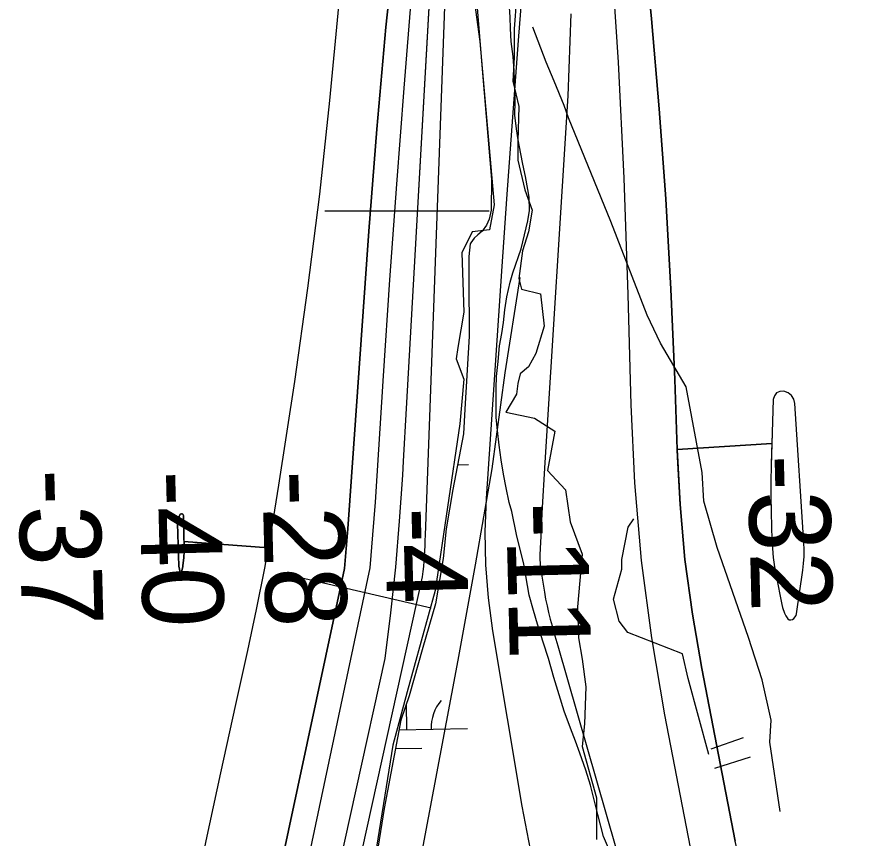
# Model space of a CAD drawing. Extents: x 3925854 to 3964121, y 224593 to 250589.
# Drawn here: x 3945031 to 3945726, y 239895 to 240571 of the extents above; entities that cross this region are included whole.
import ezdxf

# ---------------------------------------------------------------- set-up
doc = ezdxf.new("R2010")
doc.units = 0
for name, color, linetype in [('V-LEVE-TOET', 7, 'Continuous'), ('V-RIVR-EDGE', 7, 'Continuous'), ('V-RIVR-RANG', 7, 'Continuous'), ('V-RRAP-FSHR', 7, 'Continuous'), ('V-TOPO-DPTH', 7, 'Continuous'), ('V-TOPO-MINR', 7, 'Continuous'), ('V-WETL-SWMP', 7, 'Continuous')]:
    doc.layers.add(name, color=color, linetype=linetype)

msp = doc.modelspace()

# ---------------------------------------------------------------- linework, layer by layer
at = {"layer": 'V-LEVE-TOET'}
for p, q in [((3945420.097, 240410.848), (3945284.819, 240410.729)), ((3945372.172, 240083.938), (3945256.323, 240110.826)), ((3945600.835, 239963.524), (3945583.853, 240026.17)), ((3945602.861, 239968.214), (3945629.558, 239977.665)), ((3945605.89, 239952.374), (3945635.17, 239961.799))]:
    msp.add_line(p, q, dxfattribs=at)
for points in [[(3945659.785, 239916.825), (3945651.101, 239973.764), (3945652.355, 239991.837), (3945644.796, 240025.203), (3945633.603, 240059.825), (3945607.774, 240134.116), (3945596.921, 240172.227), (3945595.494, 240195.804), (3945582.241, 240266.317), (3945561.028, 240302.103), (3945550.02, 240325.17), (3945520.269, 240402.238), (3945485.435, 240487.72), (3945481.891, 240497.88), (3945473.71, 240517.846), (3945466.849, 240533.451), (3945456.111, 240562.23)], [(3945583.853, 240026.17), (3945579.2, 240046.435), (3945534.238, 240063.927), (3945527.191, 240073.424), (3945522.362, 240091.409), (3945529.307, 240116.112), (3945529.391, 240124.169), (3945534.38, 240150.869), (3945539.162, 240157.506)]]:
    msp.add_lwpolyline(points, dxfattribs=at)
at = {"layer": 'V-RIVR-EDGE'}
for points in [[(3945358.155, 241213.322), (3945377.046, 240948.836), (3945384.131, 240802.424), (3945395.151, 240665.458), (3945405.384, 240600.91), (3945412.469, 240550.532), (3945424.276, 240415.927), (3945420.34, 240395.461), (3945406.171, 240393.887), (3945397.513, 240376.569), (3945399.087, 240327.765), (3945394.364, 240298.64), (3945392.79, 240289.194), (3945399.087, 240272.664), (3945395.938, 240235.667), (3945375.472, 240098.701), (3945352.644, 240015.262), (3945340.837, 239971.181), (3945325.094, 239873.573), (3945284.948, 239657.891), (3945260.546, 239558.708), (3945201.509, 239254.864), (3945178.682, 239129.705), (3945119.644, 238862.07)], [(3945442.621, 240586.513), (3945440.655, 240560.957), (3945440.655, 240537.368), (3945439.672, 240517.71), (3945444.587, 240497.069), (3945443.604, 240468.565), (3945443.604, 240452.839), (3945449.501, 240428.266), (3945455.398, 240411.557), (3945452.45, 240393.865), (3945447.535, 240378.139), (3945444.587, 240355.532), (3945446.552, 240346.686), (3945462.279, 240342.755), (3945465.227, 240316.216), (3945458.347, 240293.61), (3945452.45, 240282.798), (3945445.569, 240276.9), (3945443.604, 240269.037), (3945442.621, 240260.191), (3945433.775, 240245.448), (3945457.364, 240240.533), (3945474.073, 240229.721), (3945468.176, 240197.286), (3945482.919, 240181.56), (3945486.851, 240155.021), (3945496.68, 240128.483), (3945492.748, 240085.236), (3945493.731, 240059.681), (3945496.68, 240041.988), (3945499.629, 240019.382), (3945498.646, 239988.912), (3945496.68, 239970.237), (3945508.475, 239927.972), (3945508.475, 239893.571)]]:
    msp.add_lwpolyline(points, dxfattribs=at)
at = {"layer": 'V-RRAP-FSHR'}
msp.add_lwpolyline([(3945160.841, 238864.481), (3945181.618, 238941.732), (3945201.145, 239019.304), (3945219.145, 239097.253), (3945234.464, 239175.769), (3945248.303, 239254.557), (3945261.424, 239333.473), (3945275.5, 239412.311), (3945288.779, 239491.118), (3945303.773, 239569.695), (3945319.141, 239648.206), (3945334.466, 239726.724), (3945349.781, 239805.244), (3945364.83, 239883.818), (3945379.788, 239962.406), (3945394.606, 240041.211), (3945408.796, 240119.751), (3945422.579, 240198.642), (3945433.143, 240277.804), (3945445.662, 240356.361)], dxfattribs=at)
at = {"layer": 'V-TOPO-DPTH'}
for points in [[(3945622.668, 239892.343), (3945595.043, 240034.436), (3945587.449, 240079.187), (3945581.292, 240124.1), (3945577.29, 240169.257), (3945574.724, 240214.575), (3945572.838, 240272.374), (3945569.701, 240346.668), (3945565.614, 240420.901), (3945560.105, 240495.042), (3945553.647, 240569.121), (3945522.628, 240889.417), (3945518.242, 240901.514), (3945511.507, 240910.884), (3945501.246, 240916.163), (3945488.634, 240918.716), (3945473.2, 240917.471), (3945457.854, 240915.636), (3945442.64, 240912.916), (3945427.514, 240909.605), (3945404.734, 240903.924), (3945392.342, 240898.155), (3945382.269, 240890.325)], [(3945652.853, 240219.537), (3945574.724, 240214.575), (3945572.838, 240272.374), (3945569.701, 240346.668), (3945565.614, 240420.901), (3945560.105, 240495.042), (3945553.647, 240569.121), (3945522.628, 240889.417), (3945518.242, 240901.514), (3945511.507, 240910.884), (3945501.246, 240916.163), (3945488.634, 240918.716), (3945473.2, 240917.471), (3945457.854, 240915.636), (3945442.64, 240912.916), (3945427.514, 240909.605), (3945404.734, 240903.924), (3945392.342, 240898.155), (3945382.269, 240890.325)], [(3945079.171, 239086.627), (3945133.342, 239136.688), (3945162.718, 239262.687), (3945163.374, 239265.574), (3945164.007, 239268.465), (3945164.608, 239271.364), (3945165.186, 239274.267), (3945165.74, 239277.176), (3945166.283, 239280.086), (3945166.811, 239282.999), (3945167.328, 239285.914), (3945334.284, 240042.622), (3945338.985, 240080.256), (3945343.092, 240117.946), (3945346.309, 240155.724), (3945348.932, 240193.558), (3945349.586, 240204.94), (3945352.082, 240248.51), (3945354.567, 240292.08), (3945357.035, 240335.652), (3945359.492, 240379.223), (3945387.62, 240879.833), (3945389.563, 240887.136), (3945392.897, 240893.289)], [(3945382.269, 240890.325), (3945375.675, 240879.403), (3945371.401, 240866.419), (3945353.948, 240729.516), (3945344.014, 240645.92), (3945335.034, 240562.229), (3945327.483, 240478.398), (3945320.885, 240394.472), (3945303.717, 240149.355), (3945302.417, 240133.051), (3945300.908, 240116.768), (3945125.024, 239293.971)], [(3945382.269, 240890.325), (3945375.675, 240879.403), (3945371.401, 240866.419), (3945353.948, 240729.516), (3945344.014, 240645.92), (3945335.034, 240562.229), (3945327.483, 240478.398), (3945320.885, 240394.472), (3945303.717, 240149.355), (3945302.417, 240133.051), (3945300.908, 240116.768), (3945125.024, 239293.971)], [(3945133.342, 239136.688), (3945162.718, 239262.687), (3945163.374, 239265.574), (3945164.007, 239268.465), (3945164.608, 239271.364), (3945165.186, 239274.267), (3945165.74, 239277.176), (3945166.283, 239280.086), (3945166.811, 239282.999), (3945167.328, 239285.914), (3945334.284, 240042.622), (3945338.985, 240080.256), (3945343.092, 240117.946), (3945346.309, 240155.724), (3945348.932, 240193.558), (3945349.586, 240204.94), (3945352.082, 240248.51), (3945354.567, 240292.08), (3945357.035, 240335.652), (3945359.492, 240379.223), (3945384.383, 240822.213), (3945384.759, 240828.906), (3945400.159, 240828.84), (3945399.952, 240820.735)], [(3945187.123, 239892.52), (3945199.08, 239948.652), (3945211.366, 240004.716), (3945221.319, 240049.193), (3945228.525, 240083.032), (3945235.263, 240116.959), (3945241.299, 240151.019), (3945246.867, 240185.166), (3945259.89, 240270.573), (3945270.821, 240347.584), (3945280.69, 240424.719), (3945288.965, 240502.042), (3945296.178, 240579.489)], [(3945238.242, 240133.769), (3945241.299, 240151.019), (3945246.867, 240185.166), (3945259.89, 240270.573), (3945270.821, 240347.584), (3945280.69, 240424.719), (3945288.965, 240502.042), (3945296.178, 240579.489)], [(3945487.39, 240573.115), (3945484.699, 240505.623), (3945465.89, 240203.929), (3945465.058, 240190.074), (3945464.27, 240176.216), (3945463.546, 240162.355), (3945462.865, 240148.491), (3945461.899, 240127.837), (3945461.847, 240124.306), (3945461.945, 240120.783), (3945462.269, 240117.274), (3945462.742, 240113.775), (3945465.536, 240097.14), (3945466.559, 240091.555), (3945467.692, 240085.993), (3945468.989, 240080.468), (3945470.396, 240074.967), (3945471.897, 240069.487), (3945473.414, 240064.011), (3945474.956, 240058.543), (3945476.515, 240053.079), (3945579.608, 239694.654)], [(3945487.39, 240573.115), (3945484.699, 240505.623), (3945465.89, 240203.929), (3945465.058, 240190.074), (3945464.27, 240176.216), (3945463.546, 240162.355), (3945462.865, 240148.491), (3945461.899, 240127.837), (3945461.847, 240124.306), (3945461.945, 240120.783), (3945462.269, 240117.274), (3945462.742, 240113.775), (3945465.536, 240097.14), (3945466.559, 240091.555), (3945467.692, 240085.993), (3945468.989, 240080.468), (3945470.396, 240074.967), (3945471.897, 240069.487), (3945473.414, 240064.011), (3945474.956, 240058.543), (3945476.515, 240053.079), (3945579.608, 239694.654)], [(3945652.65, 240212.908), (3945652.295, 240201.264), (3945652.04, 240188.653), (3945651.957, 240176.043), (3945652.133, 240163.433), (3945652.482, 240150.824), (3945652.865, 240140.751), (3945653.327, 240133.199), (3945654.02, 240125.674), (3945655.061, 240118.189), (3945656.332, 240110.731), (3945660.937, 240087.05), (3945661.528, 240084.621), (3945663.219, 240079.947), (3945664.319, 240077.702), (3945666.085, 240075.193), (3945667.143, 240074.552), (3945668.378, 240074.459), (3945669.729, 240074.733), (3945671.007, 240075.612), (3945672.736, 240077.975), (3945673.187, 240079.458), (3945678.32, 240115.312), (3945678.949, 240120.938), (3945679.344, 240126.573), (3945679.391, 240132.222), (3945679.205, 240137.88), (3945671.876, 240252.502), (3945670.835, 240256.169), (3945669.088, 240259.212), (3945666.282, 240261.319), (3945662.772, 240262.803), (3945659.426, 240262.455), (3945656.733, 240261.295)], [(3945656.733, 240261.295), (3945655.019, 240258.916), (3945653.957, 240255.724), (3945652.295, 240201.264), (3945652.04, 240188.653), (3945651.957, 240176.043), (3945652.133, 240163.433), (3945652.482, 240150.824), (3945652.865, 240140.751), (3945653.327, 240133.199), (3945654.02, 240125.674), (3945655.061, 240118.189), (3945656.332, 240110.731), (3945660.937, 240087.05), (3945661.528, 240084.621), (3945663.219, 240079.947), (3945664.319, 240077.702), (3945666.085, 240075.193), (3945667.143, 240074.552), (3945668.378, 240074.459), (3945669.729, 240074.733), (3945671.007, 240075.612), (3945672.736, 240077.975), (3945673.187, 240079.458), (3945678.32, 240115.312), (3945678.949, 240120.938), (3945679.344, 240126.573), (3945679.391, 240132.222), (3945679.205, 240137.88), (3945671.876, 240252.502), (3945670.835, 240256.169), (3945669.088, 240259.212), (3945666.282, 240261.319), (3945662.772, 240262.803), (3945659.426, 240262.455), (3945656.733, 240261.295)], [(3945656.733, 240261.295), (3945655.019, 240258.916), (3945653.957, 240255.724), (3945652.853, 240219.537)], [(3946535.235, 239352.689), (3945884.086, 239186.784), (3945883.307, 239189.346), (3945878.151, 239207.888), (3945873.664, 239226.604), (3945869.623, 239245.435), (3945862.419, 239282.22), (3945862.314, 239282.745), (3945862.206, 239283.27), (3945861.981, 239284.317), (3945861.604, 239286.425), (3945636.362, 239849.718), (3945630.635, 239863.506), (3945626.216, 239877.767), (3945622.668, 239892.343), (3945595.043, 240034.436), (3945587.449, 240079.187), (3945581.292, 240124.1), (3945577.29, 240169.257), (3945575.073, 240208.417), (3945574.724, 240214.575), (3945652.853, 240219.537), (3945652.65, 240212.908)], [(3945163.879, 240157.723), (3945163.473, 240155.773), (3945163.325, 240153.741), (3945164.399, 240118.509), (3945165.597, 240113.798), (3945165.906, 240113.463), (3945166.214, 240113.32), (3945166.521, 240113.465), (3945166.828, 240113.802), (3945167.797, 240118.241), (3945167.926, 240119.156), (3945168.406, 240123.362), (3945168.632, 240125.773), (3945168.859, 240130.606), (3945168.86, 240133.028), (3945168.323, 240160.458), (3945167.881, 240161.318), (3945167.32, 240161.807), (3945166.579, 240161.738), (3945165.719, 240161.298), (3945163.879, 240157.723)], [(3945238.076, 240132.835), (3945238.242, 240133.769), (3945168.744, 240138.944), (3945168.767, 240137.766), (3945168.86, 240133.028), (3945168.859, 240130.606), (3945168.632, 240125.773), (3945168.406, 240123.362), (3945167.926, 240119.156), (3945167.797, 240118.241), (3945166.828, 240113.802), (3945166.521, 240113.465), (3945166.214, 240113.32), (3945165.906, 240113.463), (3945165.597, 240113.798), (3945164.399, 240118.509), (3945163.325, 240153.741), (3945163.473, 240155.773), (3945163.879, 240157.723)], [(3945163.879, 240157.723), (3945165.719, 240161.298), (3945166.579, 240161.738), (3945167.32, 240161.807), (3945167.881, 240161.318), (3945168.323, 240160.458), (3945168.744, 240138.944), (3945238.242, 240133.769)], [(3944948.202, 238955.851), (3945050.084, 239272.016), (3945051.864, 239276.071), (3945054.107, 239279.778), (3945057.045, 239282.963), (3945060.447, 239285.8), (3945066.451, 239289.849), (3945068.634, 239291.611), (3945070.349, 239293.767), (3945070.943, 239295.494), (3945164.528, 239779.981), (3945175.661, 239836.285), (3945187.123, 239892.52), (3945199.08, 239948.652), (3945211.366, 240004.716), (3945221.319, 240049.193), (3945228.525, 240083.032), (3945235.263, 240116.959), (3945238.076, 240132.835)]]:
    msp.add_lwpolyline(points, dxfattribs=at)
at = {"layer": 'V-TOPO-MINR'}
for points in [[(3945382.269, 240890.325), (3945392.342, 240898.155), (3945404.734, 240903.924), (3945427.514, 240909.605), (3945442.64, 240912.916), (3945457.854, 240915.636), (3945473.2, 240917.471), (3945488.634, 240918.716), (3945501.246, 240916.163), (3945511.507, 240910.884), (3945518.242, 240901.514), (3945522.628, 240889.417), (3945553.647, 240569.121), (3945560.105, 240495.042), (3945565.614, 240420.901), (3945569.701, 240346.668), (3945572.838, 240272.374), (3945574.724, 240214.575), (3945577.29, 240169.257), (3945581.292, 240124.1), (3945587.449, 240079.187), (3945595.043, 240034.436), (3945622.668, 239892.343)], [(3945387.714, 240891.779), (3945395.379, 240897.921), (3945404.931, 240902.457), (3945422.708, 240906.891), (3945434.517, 240909.475), (3945446.394, 240911.599), (3945458.374, 240913.032), (3945470.422, 240914.004), (3945480.25, 240912.005), (3945488.234, 240907.879), (3945493.455, 240900.563), (3945496.833, 240891.12), (3945512.088, 240724.516), (3945519.869, 240629.092), (3945526.381, 240533.595), (3945530.992, 240437.986), (3945534.334, 240342.304), (3945536.601, 240251.512), (3945539.818, 240187.3), (3945545.167, 240123.32), (3945553.716, 240059.689), (3945564.398, 239996.29), (3945603.534, 239794.981)], [(3945133.342, 239136.688), (3945162.718, 239262.687), (3945163.374, 239265.574), (3945164.007, 239268.465), (3945164.608, 239271.364), (3945165.186, 239274.267), (3945165.74, 239277.176), (3945166.283, 239280.086), (3945166.811, 239282.999), (3945167.328, 239285.914), (3945334.284, 240042.622), (3945338.985, 240080.256), (3945343.092, 240117.946), (3945346.309, 240155.724), (3945348.932, 240193.558), (3945349.586, 240204.94), (3945352.082, 240248.51), (3945354.567, 240292.08), (3945357.035, 240335.652), (3945359.492, 240379.223), (3945387.62, 240879.833), (3945389.563, 240887.136), (3945392.897, 240893.289)], [(3945155.778, 239131.865), (3945184.493, 239264.7), (3945185.365, 239268.842), (3945186.189, 239272.994), (3945186.972, 239277.154), (3945187.719, 239281.32), (3945215.33, 239439.401), (3945218.985, 239457.037), (3945223.362, 239474.469), (3945228.823, 239491.591), (3945365.28, 240109.87), (3945365.809, 240114.117), (3945366.264, 240118.371), (3945366.608, 240122.635), (3945366.878, 240126.906), (3945367.084, 240131.183), (3945367.278, 240135.46), (3945367.455, 240139.738), (3945367.62, 240144.017), (3945394.863, 240886.629), (3945395.97, 240891.076), (3945397.939, 240894.824)], [(3945114.556, 239142.154), (3945144.386, 239261.072), (3945145.117, 239264.618), (3945145.647, 239268.185), (3945145.874, 239271.784), (3945145.893, 239275.571), (3945145.877, 239279.284), (3945146.016, 239282.985), (3945146.385, 239286.671), (3945146.909, 239290.346), (3945321.949, 240117.352), (3945324.353, 240144.333), (3945326.373, 240171.352), (3945333.024, 240275.244), (3945338.313, 240354.22), (3945343.91, 240433.174), (3945349.969, 240512.094), (3945356.336, 240590.991), (3945379.933, 240873.073), (3945382.88, 240883.229), (3945387.714, 240891.779)], [(3945125.024, 239293.971), (3945300.908, 240116.768), (3945302.417, 240133.051), (3945303.717, 240149.355), (3945320.885, 240394.472), (3945327.483, 240478.398), (3945335.034, 240562.229), (3945344.014, 240645.92), (3945353.948, 240729.516), (3945371.401, 240866.419), (3945375.675, 240879.403), (3945382.269, 240890.325)], [(3945448.88, 240614.527), (3945443.968, 240551.305), (3945439.196, 240488.073), (3945434.636, 240424.825), (3945430.217, 240361.567), (3945417.455, 240174.373), (3945416.557, 240147.009), (3945416.938, 240119.708), (3945419.239, 240092.502), (3945422.82, 240065.358), (3945447.031, 239921.213), (3945453.796, 239885.476)], [(3945187.123, 239892.52), (3945199.08, 239948.652), (3945211.366, 240004.716), (3945221.319, 240049.193), (3945228.525, 240083.032), (3945235.263, 240116.959), (3945241.299, 240151.019), (3945246.867, 240185.166), (3945259.89, 240270.573), (3945270.821, 240347.584), (3945280.69, 240424.719), (3945288.965, 240502.042), (3945296.178, 240579.489)], [(3945487.39, 240573.115), (3945484.699, 240505.623), (3945465.89, 240203.929), (3945465.058, 240190.074), (3945464.27, 240176.216), (3945463.546, 240162.355), (3945462.865, 240148.491), (3945461.899, 240127.837), (3945461.847, 240124.306), (3945461.945, 240120.783), (3945462.269, 240117.274), (3945462.742, 240113.775), (3945465.536, 240097.14), (3945466.559, 240091.555), (3945467.692, 240085.993), (3945468.989, 240080.468), (3945470.396, 240074.967), (3945471.897, 240069.487), (3945473.414, 240064.011), (3945474.956, 240058.543), (3945476.515, 240053.079), (3945579.608, 239694.654)], [(3945656.733, 240261.295), (3945655.019, 240258.916), (3945653.957, 240255.724), (3945652.295, 240201.264), (3945652.04, 240188.653), (3945651.957, 240176.043), (3945652.133, 240163.433), (3945652.482, 240150.824), (3945652.865, 240140.751), (3945653.327, 240133.199), (3945654.02, 240125.674), (3945655.061, 240118.189), (3945656.332, 240110.731), (3945660.937, 240087.05), (3945661.528, 240084.621), (3945663.219, 240079.947), (3945664.319, 240077.702), (3945666.085, 240075.193), (3945667.143, 240074.552), (3945668.378, 240074.459), (3945669.729, 240074.733), (3945671.007, 240075.612), (3945672.736, 240077.975), (3945673.187, 240079.458), (3945678.32, 240115.312), (3945678.949, 240120.938), (3945679.344, 240126.573), (3945679.391, 240132.222), (3945679.205, 240137.88), (3945671.876, 240252.502), (3945670.835, 240256.169), (3945669.088, 240259.212), (3945666.282, 240261.319), (3945662.772, 240262.803), (3945659.426, 240262.455), (3945656.733, 240261.295)], [(3945163.879, 240157.723), (3945163.473, 240155.773), (3945163.325, 240153.741), (3945164.399, 240118.509), (3945165.597, 240113.798), (3945165.906, 240113.463), (3945166.214, 240113.32), (3945166.521, 240113.465), (3945166.828, 240113.802), (3945167.797, 240118.241), (3945167.926, 240119.156), (3945168.406, 240123.362), (3945168.632, 240125.773), (3945168.859, 240130.606), (3945168.86, 240133.028), (3945168.323, 240160.458), (3945167.881, 240161.318), (3945167.32, 240161.807), (3945166.579, 240161.738), (3945165.719, 240161.298), (3945163.879, 240157.723)]]:
    msp.add_lwpolyline(points, dxfattribs=at)
at = {"layer": 'V-WETL-SWMP'}
for p, q in [((3945393.999, 240202.138), (3945402.949, 240202.301)), ((3945352.315, 239984.102), (3945351.928, 240005.394)), ((3945345.716, 239983.982), (3945402.307, 239985.011)), ((3945342.848, 239968.496), (3945364.594, 239968.891))]:
    msp.add_line(p, q, dxfattribs=at)
for points in [[(3945409.617, 240585.035), (3945414.434, 240524.366), (3945422, 240436.939), (3945421.738, 240411.726), (3945420.047, 240404.279), (3945417.776, 240399.26), (3945414.295, 240394.253), (3945410.635, 240391.466), (3945407.578, 240388.472), (3945404.916, 240384.667), (3945404.506, 240384.066), (3945403.185, 240373.388), (3945403.207, 240356.039), (3945403.514, 240307.823), (3945400.068, 240247.945), (3945398.848, 240227.583), (3945390.101, 240181.68), (3945384.52, 240149.26), (3945382.25, 240124.874), (3945375.812, 240087.621), (3945365.354, 240051.822), (3945354.249, 240011.995), (3945347.182, 239991.895), (3945333.719, 239919.211), (3945319.696, 239831.403)], [(3945526.715, 239866.673), (3945514.311, 239896.052), (3945509.456, 239914.157), (3945506.456, 239926.393), (3945503.453, 239938.326), (3945499.647, 239950.671), (3945494.749, 239964.641), (3945491.02, 239974.665), (3945486.894, 239985.299), (3945481.896, 239999.371), (3945477.799, 240012.828), (3945473.207, 240027.098), (3945469.031, 240042.674), (3945464.53, 240056.035), (3945459.743, 240071.013), (3945456.429, 240082.142), (3945453.031, 240094.886), (3945448.552, 240120.149), (3945442.553, 240144.62), (3945438.615, 240163.724), (3945436.574, 240171.109), (3945433.975, 240183.138), (3945431.872, 240194.255), (3945429.877, 240206.178), (3945428.387, 240218.095), (3945426.9, 240230.315), (3945425.802, 240241.119), (3945425.751, 240255.644), (3945425.749, 240265.226), (3945426.15, 240274.704), (3945427.388, 240287.097), (3945428.631, 240299.995), (3945430.351, 240310.164), (3945431.957, 240319.124), (3945433.074, 240329.603), (3945434.598, 240340.379), (3945437.346, 240352.455), (3945439.543, 240360.097), (3945446.302, 240379.696), (3945451.789, 240402.939), (3945453.288, 240411.396), (3945452.897, 240422.293), (3945451.855, 240428.759), (3945449.848, 240439.472), (3945447.731, 240449.378), (3945446.006, 240458.07), (3945444.006, 240469.489), (3945442.589, 240478.682), (3945441.292, 240489.791), (3945441.409, 240501.086), (3945441.115, 240511.68), (3945440.763, 240526.309), (3945439.878, 240538.22), (3945438.089, 240550.544), (3945437.493, 240561.141), (3945437.287, 240570.423), (3945436.607, 240582.635)]]:
    msp.add_lwpolyline(points, dxfattribs=at)
msp.add_arc((3945407.54, 239985.581), 35.246, 140.269876, 181.813534, dxfattribs=at)

# ---------------------------------------------------------------- texts
at = {"layer": 'V-RIVR-RANG'}
for s, p in [('-32', (3945632.961, 240209.788)), ('-37', (3945032.195, 240197.955)), ('-40', (3945131.755, 240196.818)), ('-28', (3945233.155, 240197.05)), ('-4', (3945333.957, 240166.613)), ('-11', (3945433.885, 240170.721))]:
    msp.add_text(s, height=67, rotation=271.447, dxfattribs=at).set_placement(p)

doc.saveas('drawing.dxf')
